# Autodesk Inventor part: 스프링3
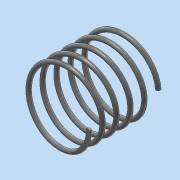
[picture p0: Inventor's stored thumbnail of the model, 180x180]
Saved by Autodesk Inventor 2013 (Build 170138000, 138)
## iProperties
Created: 2015-11
Part Number: 스프링3
Material: 강철, 탄소
Document SubType Name: Modeling
Designer: dgall
Density: 7.87 g/cm^3
Mass: 1.54771 g
Surface Area: 7.88792 cm^2
Volume: 0.19666 cm^3
Author: dgall
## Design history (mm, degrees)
sketch "스케치1"
  geometry: L1 (0, 0)-(8, 0); L2 (0, 0)-(0, 16.67); L3 (0, 16.67)-(8, 16.67); C1 r 0.5 at (8, 0)
  constraints: 6 end point, 2 perpendicular, 1 centre point, 1 coincident, 1 horizontal, 1 vertical alignment
  dimensions: "d0" = 16 diameter of L1.end L2; "d2" = 16.66987 distance of L1.start L2.end (derived); "d3" = 1 diameter of C1
feature "코일1" sketch "스케치1" pitch "d4" = 10; turns "d6" = 5; dims "d5" = 16.66987 (= d2), "d7" = 0, angle "d8" = 90 deg, angle "d9" = 90 deg, "d10" = 0, "d11" = 0
node "작업 평면1"
feature "분할1"
feature "분할2"
node "솔리드1"
other parameters: "d12" = 25
